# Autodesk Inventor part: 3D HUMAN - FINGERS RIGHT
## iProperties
Category: PART
Company: Cross Bros.
Shininess: 64.0
Length Units: 11272
Angle Units: 11279
Time Units: 11290
Mass Units: 11286
Length Display Precision: 3
Angle Display Precision: 2
Compacted: True
Part Number: 3D HUMAN - FINGERS RIGHT
Document SubType Name: Modeling
Created: 2003-03
Designer: MVF
Catalog Web Link: www.crossbros.com
Density: 0.0
Volumn: 0.0
Area: 0.0
PropertySet Name: Model Information
Control State: 0
Master: False
Checked Out: False
Author: MVF
Title: iMike
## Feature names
1. Derived Body1 [Tagging]
